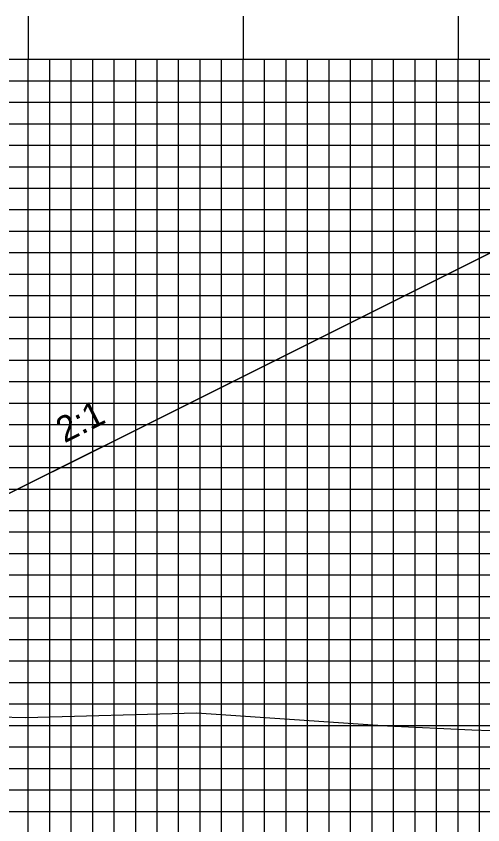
# Model space of a CAD drawing. Extents: x 1785795 to 1786139, y 442591 to 442811.
# Drawn here: x 1785910.49 to 1785932.2, y 442618.04 to 442655.67 of the extents above; entities that cross this region are included whole.
import ezdxf

# ---------------------------------------------------------------- set-up
doc = ezdxf.new("R2010")
doc.units = 0
for name, color, linetype in [('ANNOTATION', 7, 'Continuous'), ('D_Roadway_Centerline', 7, 'Continuous'), ('D_Roadway_SlopeLines', 7, 'Continuous'), ('MAJOR', 7, 'Continuous'), ('MINOR', 7, 'Continuous'), ('S_Roadway_Centerline', 7, 'Continuous')]:
    doc.layers.add(name, color=color, linetype=linetype)

msp = doc.modelspace()

# ---------------------------------------------------------------- linework, layer by layer
at = {"layer": 'D_Roadway_Centerline'}
msp.add_lwpolyline([(1785891.131, 442623.946), (1785933.236, 442644.998), (1785938.052, 442647.406), (1785941.052, 442647.526), (1785949.052, 442647.846), (1785961.052, 442648.11), (1785973.052, 442648.374), (1785981.052, 442648.054), (1785984.052, 442647.934), (1785988.802, 442645.559), (1786043.1, 442618.41)], dxfattribs=at)
at = {"layer": 'D_Roadway_SlopeLines'}
msp.add_lwpolyline([(1785938.052, 442647.406), (1785891.131, 442623.946)], dxfattribs=at)
at = {"layer": 'MAJOR'}
for p, q in [((1785911.052, 442655.669), (1785911.052, 442653.665)), ((1785921.052, 442655.669), (1785921.052, 442653.665)), ((1785931.052, 442655.669), (1785931.052, 442653.665)), ((1785821.052, 442653.665), (1786101.052, 442653.665)), ((1785821.052, 442653.665), (1786101.052, 442653.665)), ((1785911.052, 442608.665), (1785911.052, 442653.665)), ((1785921.052, 442608.665), (1785921.052, 442653.665)), ((1785931.052, 442608.665), (1785931.052, 442653.665)), ((1785821.052, 442648.665), (1786101.052, 442648.665)), ((1785821.052, 442643.665), (1786101.052, 442643.665)), ((1785821.052, 442638.665), (1786101.052, 442638.665)), ((1785821.052, 442633.665), (1786101.052, 442633.665)), ((1785821.052, 442628.665), (1786101.052, 442628.665)), ((1785821.052, 442623.665), (1786101.052, 442623.665)), ((1785821.052, 442618.665), (1786101.052, 442618.665))]:
    msp.add_line(p, q, dxfattribs=at)
at = {"layer": 'MINOR'}
for p, q in [((1785912.052, 442608.665), (1785912.052, 442653.665)), ((1785913.052, 442608.665), (1785913.052, 442653.665)), ((1785914.052, 442608.665), (1785914.052, 442653.665)), ((1785915.052, 442608.665), (1785915.052, 442653.665)), ((1785916.052, 442608.665), (1785916.052, 442653.665)), ((1785917.052, 442608.665), (1785917.052, 442653.665)), ((1785918.052, 442608.665), (1785918.052, 442653.665)), ((1785919.052, 442608.665), (1785919.052, 442653.665)), ((1785920.052, 442608.665), (1785920.052, 442653.665)), ((1785922.052, 442608.665), (1785922.052, 442653.665)), ((1785923.052, 442608.665), (1785923.052, 442653.665)), ((1785924.052, 442608.665), (1785924.052, 442653.665)), ((1785925.052, 442608.665), (1785925.052, 442653.665)), ((1785926.052, 442608.665), (1785926.052, 442653.665)), ((1785927.052, 442608.665), (1785927.052, 442653.665)), ((1785928.052, 442608.665), (1785928.052, 442653.665)), ((1785929.052, 442608.665), (1785929.052, 442653.665)), ((1785930.052, 442608.665), (1785930.052, 442653.665)), ((1785932.052, 442608.665), (1785932.052, 442653.665)), ((1785821.052, 442652.665), (1786101.052, 442652.665)), ((1785821.052, 442651.665), (1786101.052, 442651.665)), ((1785821.052, 442650.665), (1786101.052, 442650.665)), ((1785821.052, 442649.665), (1786101.052, 442649.665)), ((1785821.052, 442647.665), (1786101.052, 442647.665)), ((1785821.052, 442646.665), (1786101.052, 442646.665)), ((1785821.052, 442645.665), (1786101.052, 442645.665)), ((1785821.052, 442644.665), (1786101.052, 442644.665)), ((1785821.052, 442642.665), (1786101.052, 442642.665)), ((1785821.052, 442641.665), (1786101.052, 442641.665)), ((1785821.052, 442640.665), (1786101.052, 442640.665)), ((1785821.052, 442639.665), (1786101.052, 442639.665)), ((1785821.052, 442637.665), (1786101.052, 442637.665)), ((1785821.052, 442636.665), (1786101.052, 442636.665)), ((1785821.052, 442635.665), (1786101.052, 442635.665)), ((1785821.052, 442634.665), (1786101.052, 442634.665)), ((1785821.052, 442632.665), (1786101.052, 442632.665)), ((1785821.052, 442631.665), (1786101.052, 442631.665)), ((1785821.052, 442630.665), (1786101.052, 442630.665)), ((1785821.052, 442629.665), (1786101.052, 442629.665)), ((1785821.052, 442627.665), (1786101.052, 442627.665)), ((1785821.052, 442626.665), (1786101.052, 442626.665)), ((1785821.052, 442625.665), (1786101.052, 442625.665)), ((1785821.052, 442624.665), (1786101.052, 442624.665)), ((1785821.052, 442622.665), (1786101.052, 442622.665)), ((1785821.052, 442621.665), (1786101.052, 442621.665)), ((1785821.052, 442620.665), (1786101.052, 442620.665)), ((1785821.052, 442619.665), (1786101.052, 442619.665))]:
    msp.add_line(p, q, dxfattribs=at)
at = {"layer": 'S_Roadway_Centerline'}
msp.add_lwpolyline([(1785821.052, 442626.887), (1785826.826, 442626.633), (1785831.378, 442626.401), (1785844.916, 442626.197), (1785855.765, 442625.575), (1785865.079, 442625.067), (1785882.982, 442624.387), (1785886.4, 442624.106), (1785896.825, 442623.752), (1785907.147, 442623.131), (1785910.934, 442623.031), (1785918.877, 442623.243), (1785927.769, 442622.644), (1785931.687, 442622.463), (1785935.233, 442622.339)], dxfattribs=at)

# ---------------------------------------------------------------- texts
at = {"layer": 'ANNOTATION'}
msp.add_text('2:1', height=1.2, rotation=26.5651, dxfattribs=at).set_placement((1785912.736, 442635.785))

doc.saveas('drawing.dxf')
